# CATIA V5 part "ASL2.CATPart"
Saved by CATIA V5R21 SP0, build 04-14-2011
Part number: ASL2.SLDPRT
Bounding box of the stored display mesh (mm): x -1.365 to 1.365, y -1.5 to 1.5, z -0.78 to 0
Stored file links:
  C:\Users\user\Desktop\CATIA文件\0-最新文件\ASL2\ASL2.CATPart
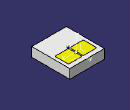
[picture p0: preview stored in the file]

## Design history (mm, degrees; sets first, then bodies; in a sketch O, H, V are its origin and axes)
AxisSystem1: origin (0, 0.615, 0), X (1, 0, 0), Y (0, 1, 0), Z (0, 0, 1)
Set1
  DatumSurface1 to DatumSurface47
  Line1 to Line9: stored without definition
  Circle1: stored without definition
  Line10: stored without definition
  Circle2: stored without definition
  Line11: stored without definition
  Circle3: stored without definition
  Line12: stored without definition
  Circle4: stored without definition
  Line13: stored without definition
  Circle5: stored without definition
  Line14: stored without definition
  Circle6: stored without definition
  Line15: stored without definition
  Circle7: stored without definition
  Line16: stored without definition
  Circle8: stored without definition
  Line17 to Line20: stored without definition
  Circle9: stored without definition
  Line21: stored without definition
  Circle10: stored without definition
  Line22: stored without definition
  Circle11: stored without definition
  Line23 to Line25: stored without definition
  Circle12: stored without definition
  Line26: stored without definition
  Circle13: stored without definition
  Line27: stored without definition
  Circle14: stored without definition
  Line28: stored without definition
  Circle15: stored without definition
  Line29 to Line41: stored without definition
  Circle16: stored without definition
  Line42 to Line45: stored without definition
  Circle17: stored without definition
  Line46 to Line48: stored without definition
  Circle18: stored without definition
  Line49 to Line51: stored without definition
  Circle19: stored without definition
  Line52 to Line64: stored without definition
  Circle20: stored without definition
  Line65 to Line67: stored without definition
  Circle21: stored without definition
  Line68 to Line70: stored without definition
  Circle22: stored without definition
  Line71: stored without definition
  Line72: stored without definition
  Circle23: stored without definition
  Line73 to Line76: stored without definition
  Circle24: stored without definition
  Line77 to Line79: stored without definition
  Circle25: stored without definition
  Line80 to Line82: stored without definition
  Circle26: stored without definition
  Line83: stored without definition
  Line84: stored without definition
  Circle27: stored without definition
  Line85 to Line88: stored without definition
  Circle28: stored without definition
  Line89 to Line91: stored without definition
  Circle29: stored without definition
  Line92 to Line94: stored without definition
  Circle30: stored without definition
  Line95: stored without definition
  Point1 "几何中心": type Between, FirstPoint vertex [face of DatumSurface7], SecondPoint vertex [face of DatumSurface3], Ratio 0.5
  Point2 "发光中心（测试原点）": type Between, FirstPoint vertex [face of DatumSurface7], SecondPoint vertex [face of DatumSurface1], Ratio 0.5
  Point3 "虚拟坐标": (-0.011, 0.0061, -0.0299), relative to Point2, in AxisSystem1
Body1 (main body)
